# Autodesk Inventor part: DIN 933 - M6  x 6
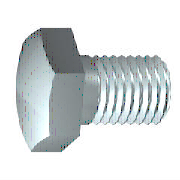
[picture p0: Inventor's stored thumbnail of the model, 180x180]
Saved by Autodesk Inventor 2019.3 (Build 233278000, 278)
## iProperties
Created: 2018-01
Part Number: DIN 933 - M6  x 6
Material: Ocel, měkká
Description: Šestihranný šroub
Document SubType Name: Modeling
Standard: DIN 933
Designer: B-hon
Standards Organization: DIN
Language: cs-CZ
Size Designation: M6  x 6
Categories: <MemberInstance><Categories><Category DisplayName="Spojovací materiál" InternalName="e4da775c-781d-43d5-af7c-5136215cf5a6" Mnemonic="FSTN"><Category DisplayName
Density: 7.85 g/cm^3
Appearance: Pololeštěná
IsCustomPart: 0
Author: B-hon
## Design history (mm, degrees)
sketch "Náčrt1"
  geometry: L1 (0, 4.35)-(0, 2.729); L2 (3, 3)-(6, 3); L3 (6, 3)-(6, 0); L4 (6, 0)-(-0.5, 0); L5 (-1.8, 0)-(7.3, 0) reference; L6 (-0.5, 0)-(-0.5, 4.35); L7 (-0.5, 4.35)-(0, 4.35); L8 (3, 3)-(2.386, 2.729); L9 (2.386, 2.729)-(0, 2.729); L10 (0, -0.87)-(0, 5.22) reference
  constraints: 16 end point, 2 collinear, 2 perpendicular, 1 parallel
  dimensions: "d0" = 6 distance between parallel lines of L3 L1 (= NLG); "d1" = 3 distance from line of L2.start L3 (= GEL); "d2" = 6 diameter of L2 L4 (= GD); "d9" = 0.5001 distance between parallel lines of L6 L1 (computed from SD); "d10" = 8.7 diameter of L7 L4 (= SD2); "d13" = 0.61355 horizontal distance of L2.start L8.end (computed from GAL); "d14" = 5.45873 diameter of L9 L4 (= BDM)
revolve "Těleso" sketch "Náčrt1" stored, may be unused: angle "d12" = 90 deg
sketch "Náčrt2"
  geometry: L1 (0, 5.774)-(5, 2.887); L2 (5, 2.887)-(5, -2.887); L3 (5, -2.887)-(0, -5.774); L4 (0, -5.774)-(-5, -2.887); L5 (-5, -2.887)-(-5, 2.887); L6 (-5, 2.887)-(0, 5.774); 2 further points
  constraints: 12 end point, 1 coincident, 1 vertical, 11 other
  dimensions: "d11" = 10 distance between parallel lines of L5 L2 (= SW)
extrude "Hlava" join sketch "Náčrt2" distance "d3" = 3.5 (= KOH - SD); taper "d4" = 0 deg
sketch "Náčrt4"
  geometry: L1 (-4, 5)-(-4, 5.774); L2 (-4, 5.774)-(-3.554, 5.774); L3 (-3.554, 5.774)-(-4, 5); L4 (-4.7, 0)-(0.2, 0) reference; L5 (-0.5, 5.774)-(-4, 5.774) reference; L6 (-4, 2.887)-(-4, 5.774) reference
  constraints: 6 end point, 2 collinear, 1 perpendicular, 1 vertical
  dimensions: "d5" = 30 deg angle of L3 L1 (= ANG1); "d19" = 10 diameter of L1.start L4 (= SW0)
revolve "Zkosení1" sketch "Náčrt4" stored, may be unused: angle "d21" = 90 deg
workplane "Work Plane1"
body "Solid1"
feature "Závit" dims "d15" = 3 (= GEL), "d16" = 0
chamfer "Zkosení2" distance "d6" = 0.61345 (= -0.5 x SPD + 0.5 x GD); stored, may be unused: second distance "d7" = 0.61355 (computed from GUL), angle "d55" = 45 deg
other parameters: "NLG" = 6 [user parameter; used in 1 equation term], "GD" = 6 (= NND) [user parameter; used in 2 equation terms], "BDM" = 5.45873 [user parameter; used in 1 equation term], "KOH" = 4 [user parameter; used in 1 equation term], "GEL" = 3 [user parameter; used in 2 equation terms], "SW" = 10 [user parameter; used in 2 equation terms], "SW0" = 10 [user parameter; used in 1 equation term], "SPD" = 4.7731 (= NND - 1.2269 x PTC) [user parameter; used in 1 equation term], "SD2" = 8.7 [user parameter; used in 1 equation term], "SD" = 0.5 [user parameter; used in 2 equation terms], "ANG1" = 30 deg [user parameter; used in 1 equation term], "GAL" = 0.61345 (= 0.61345 x PTC) [user parameter; used in 1 equation term], "GUL" = 0.61345 (= 0.61345 x PTC) [user parameter; used in 1 equation term], "d8" = 0, "RR" = 0.25 [user parameter], "d57" = 0, "d58" = 0, "GD1" = 4.7731 (= THREADDIA - 1.2269 x PTC) [user parameter], "THREADDIA" = 6 [user parameter; used in 1 equation term], "TOA" = 30 deg [user parameter], "PTC" = 1 [user parameter; used in 5 equation terms], "NND" = 6 [user parameter; used in 2 equation terms], "E0" = 11.55 (= 1.155 x SW) [user parameter]
